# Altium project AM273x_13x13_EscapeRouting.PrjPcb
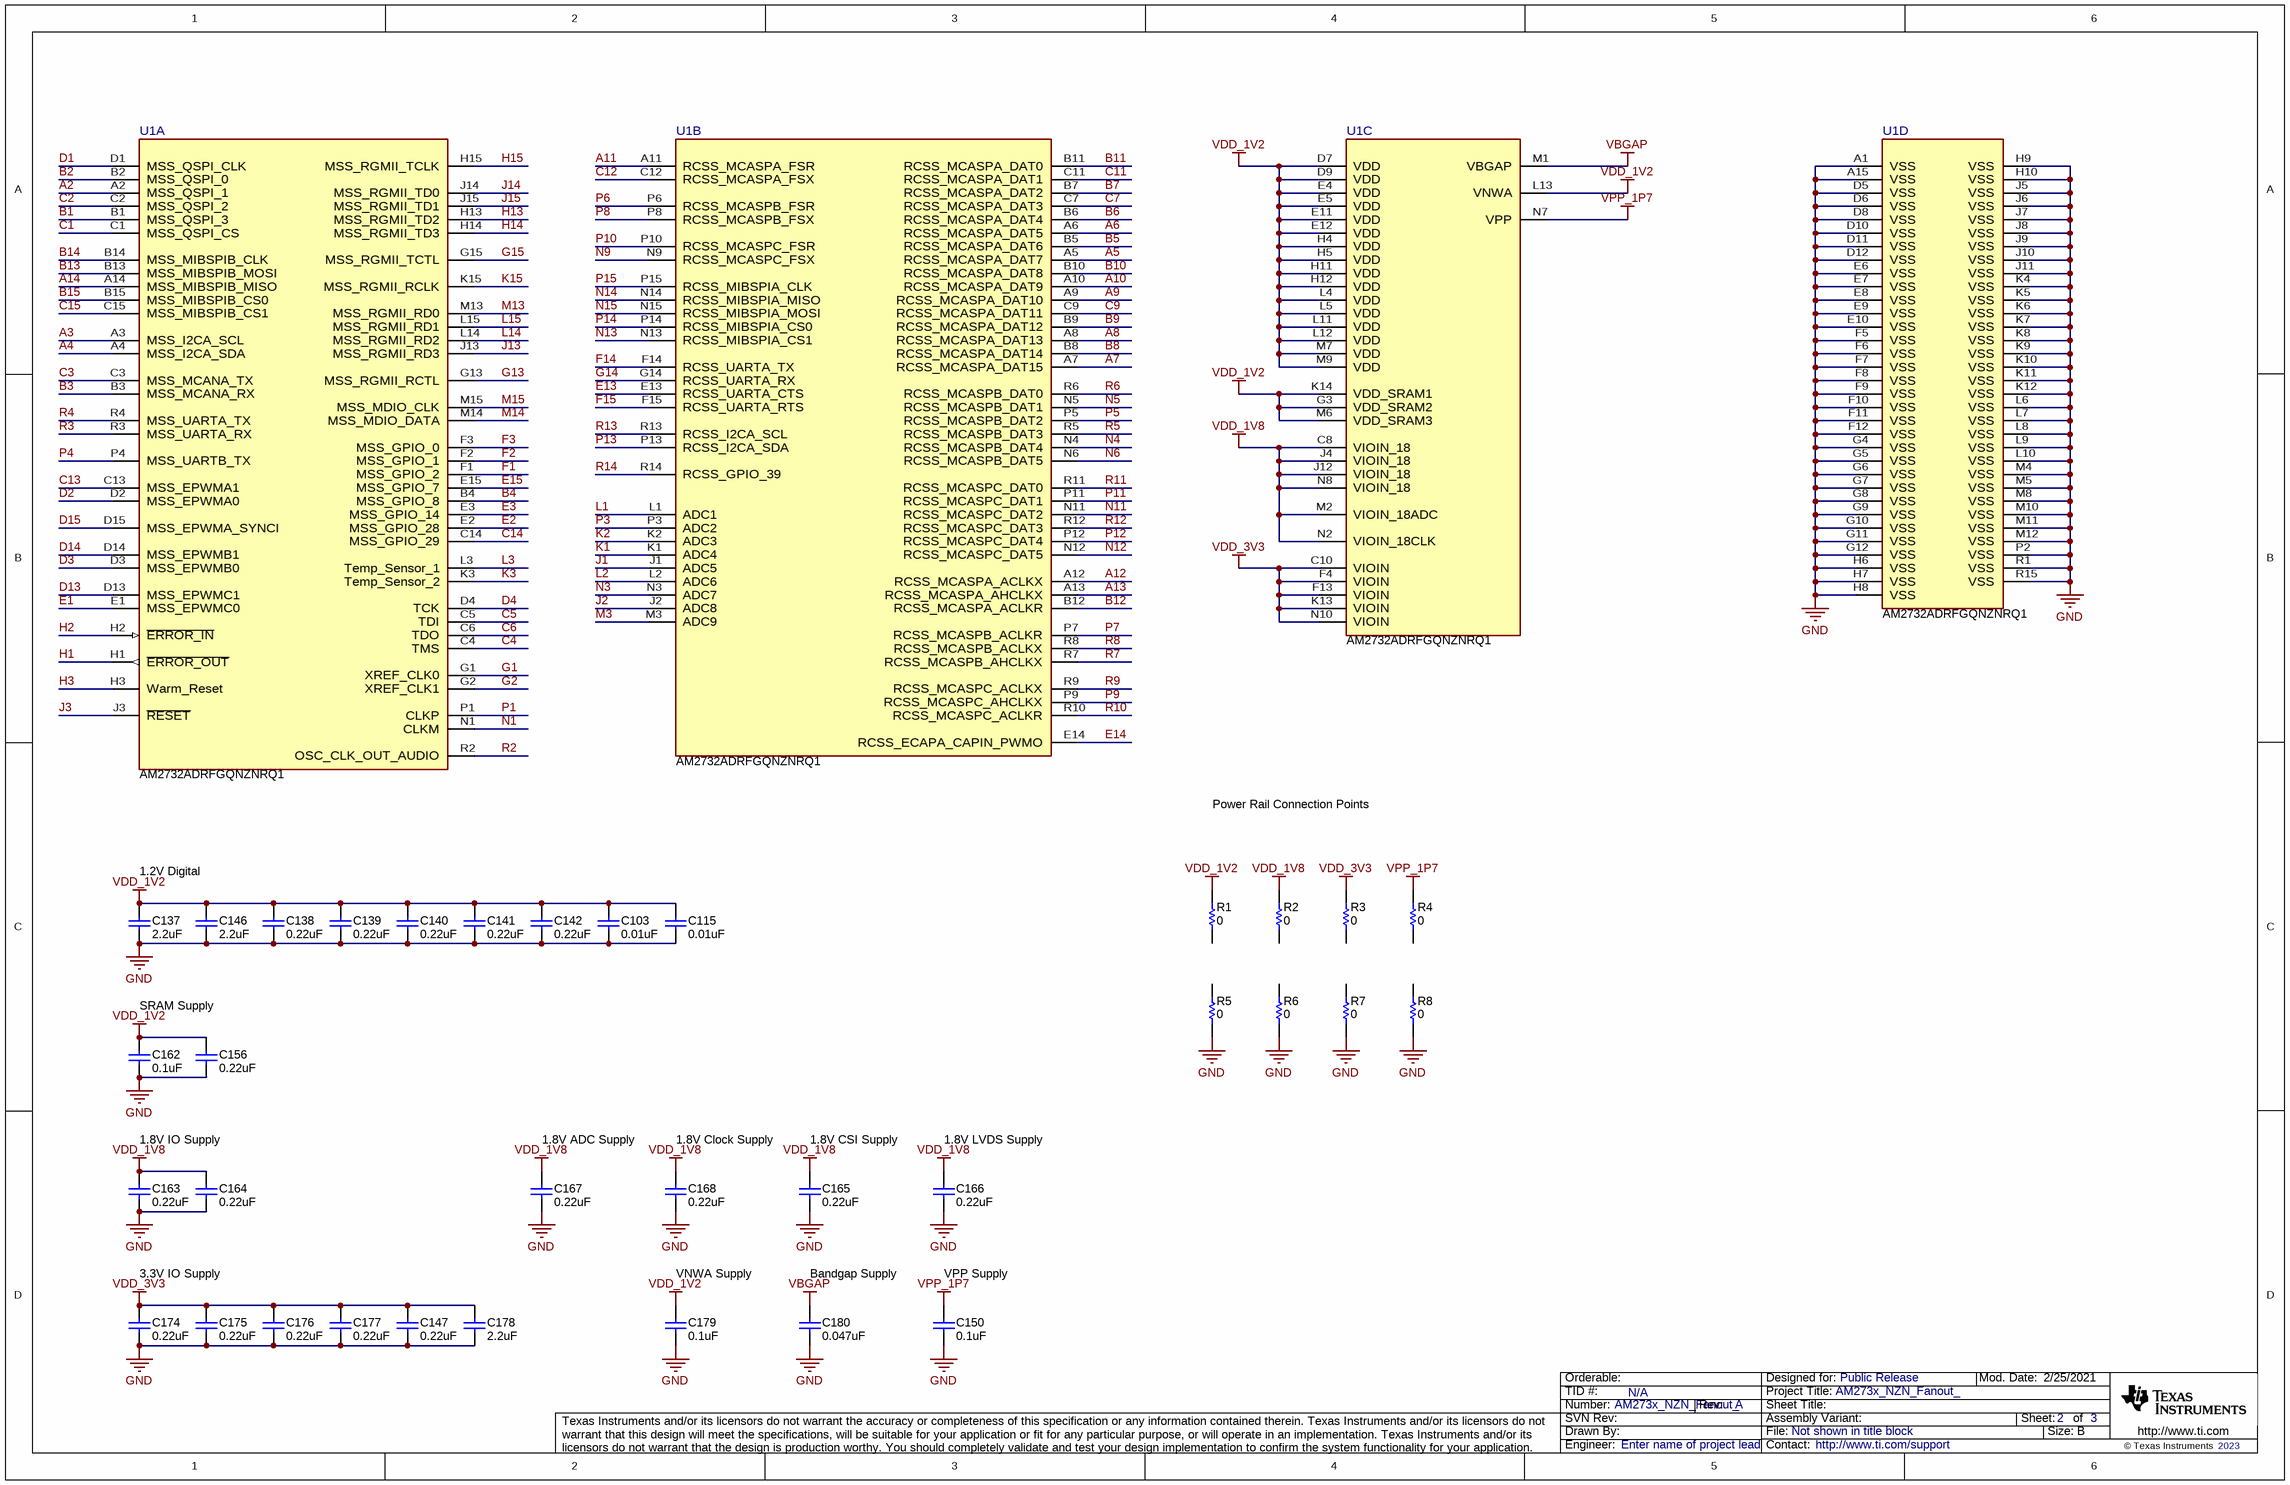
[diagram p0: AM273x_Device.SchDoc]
CopyrightYear: 2023; PCB_Layout: a02872566; PCB_Rev: A; PRJ_Customer: Public Release; PRJ_Engineer: Enter name of project lead; PRJ_Number: AM273x_NZN_Fanout_; PRJ_Title: AM273x_NZN_Fanout_; SCH_Rev: A; TechSupport: http://www.ti.com/support; TID: N/A
2 sheets, 42 parts. Net scope: global (net labels, ports and power ports of the same name join across sheets).
Board file: AM273x_13x13_EscapeRouting.PcbDoc
Sheets:
  AM273x_Device.SchDoc
  AM273x_13x13_EscapeRouting_Hardware.SchDoc

## Sheet AM273x_Device.SchDoc
size 431 x 279 mm; Date: Not shown in title block; ApprovedBy: Not shown in title block; CheckedBy: Not shown in title block; Author: Not shown in title block; CompanyName: Not shown in title block; Engineer: Not shown in title block; Organization: Not shown in title block; Address1: Not shown in title block; Address2: Not shown in title block; Address3: Not shown in title block; Address4: Not shown in title block; DocumentNumber: 2; Revision: Use project parameter SCH_Rev; SheetNumber: 2; SheetTotal: 3; PageSetup: Record=PageOptions¦CenterHorizontal=True¦CenterVertical=True¦PrintScale=1.00¦XCorrection=1.00¦YCorrection=1.00¦PrintKind=0¦BorderSize=5000000¦LeftOffset=0¦BottomOffset=0¦Orientation=2¦PaperLength=1000¦PaperWidth=1000¦Scale=100¦PaperSource=15¦PrintQuality=600¦MediaType=1¦DitherType=10¦PaperKind=Letter¦PrintScaleMode=1

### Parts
C103  ValueDisplayed: 0.01uF  [0402]  (hidden comment: CGA2B3X7R1H103K050BB)
C115  ValueDisplayed: 0.01uF  [0402]  (hidden comment: CGA2B3X7R1H103K050BB)
C137  ValueDisplayed: 2.2uF  [0603]  (hidden comment: GRM188R61C225KAAD)
C138  ValueDisplayed: 0.22uF  [0402]  (hidden comment: GRM155R71A224KE01D)
C139  ValueDisplayed: 0.22uF  [0402]  (hidden comment: GRM155R71A224KE01D)
C140  ValueDisplayed: 0.22uF  [0402]  (hidden comment: GRM155R71A224KE01D)
C141  ValueDisplayed: 0.22uF  [0402]  (hidden comment: GRM155R71A224KE01D)
C142  ValueDisplayed: 0.22uF  [0402]  (hidden comment: GRM155R71A224KE01D)
C146  ValueDisplayed: 2.2uF  [0603]  (hidden comment: GRM188R61C225KAAD)
C147  ValueDisplayed: 0.22uF  [0402]  (hidden comment: GRM155R71A224KE01D)
C150  ValueDisplayed: 0.1uF  [0402]  (hidden comment: GCM155R71C104KA55D)
C156  ValueDisplayed: 0.22uF  [0402]  (hidden comment: GRM155R71A224KE01D)
C162  ValueDisplayed: 0.1uF  [0402]  (hidden comment: GCM155R71C104KA55D)
C163  ValueDisplayed: 0.22uF  [0402]  (hidden comment: GRM155R71A224KE01D)
C164  ValueDisplayed: 0.22uF  [0402]  (hidden comment: GRM155R71A224KE01D)
C165  ValueDisplayed: 0.22uF  [0402]  (hidden comment: GRM155R71A224KE01D)
C166  ValueDisplayed: 0.22uF  [0402]  (hidden comment: GRM155R71A224KE01D)
C167  ValueDisplayed: 0.22uF  [0402]  (hidden comment: GRM155R71A224KE01D)
C168  ValueDisplayed: 0.22uF  [0402]  (hidden comment: GRM155R71A224KE01D)
C174  ValueDisplayed: 0.22uF  [0402]  (hidden comment: GRM155R71A224KE01D)
C175  ValueDisplayed: 0.22uF  [0402]  (hidden comment: GRM155R71A224KE01D)
C176  ValueDisplayed: 0.22uF  [0402]  (hidden comment: GRM155R71A224KE01D)
C177  ValueDisplayed: 0.22uF  [0402]  (hidden comment: GRM155R71A224KE01D)
C178  ValueDisplayed: 2.2uF  [0603]  (hidden comment: GRM188R61C225KAAD)
C179  ValueDisplayed: 0.1uF  [0402]  (hidden comment: GCM155R71C104KA55D)
C180  ValueDisplayed: 0.047uF  [0402]  (hidden comment: CGA2B3X7R1H473K050BB)
R1  ValueDisplayed: 0  [5106]  (hidden comment: 5106)
R2  ValueDisplayed: 0  [5106]  (hidden comment: 5106)
R3  ValueDisplayed: 0  [5106]  (hidden comment: 5106)
R4  ValueDisplayed: 0  [5106]  (hidden comment: 5106)
R5  ValueDisplayed: 0  [5106]  (hidden comment: 5106)
R6  ValueDisplayed: 0  [5106]  (hidden comment: 5106)
R7  ValueDisplayed: 0  [5106]  (hidden comment: 5106)
R8  ValueDisplayed: 0  [5106]  (hidden comment: 5106)
U1  AM2732ADRFGQNZNRQ1  [NZN0225A-MFG]  (parts A,B,C,D of 4)

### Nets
GND: C103.1 C115.1 C137.1 C138.1 C139.1 C140.1 C141.1 C142.1 C146.1 C147.1 C150.1 C156.1 C162.1 C163.1 C164.1 C165.1 C166.1 C167.1 C168.1 C174.1 C175.1 C176.1 C177.1 C178.1 C179.1 C180.1 R5.1 R6.1 R7.1 R8.1 U1.A1(VSS) U1.A15(VSS) U1.D5(VSS) U1.D6(VSS) U1.D8(VSS) U1.D10(VSS) U1.D11(VSS) U1.D12(VSS) U1.E6(VSS) U1.E7(VSS) U1.E8(VSS) U1.E9(VSS) U1.E10(VSS) U1.F5(VSS) U1.F6(VSS) U1.F7(VSS) U1.F8(VSS) U1.F9(VSS) U1.F10(VSS) U1.F11(VSS) U1.F12(VSS) U1.G4(VSS) U1.G5(VSS) U1.G6(VSS) U1.G7(VSS) U1.G8(VSS) U1.G9(VSS) U1.G10(VSS) U1.G11(VSS) U1.G12(VSS) U1.H6(VSS) U1.H7(VSS) U1.H8(VSS) U1.H9(VSS) U1.H10(VSS) U1.J5(VSS) U1.J6(VSS) U1.J7(VSS) U1.J8(VSS) U1.J9(VSS) U1.J10(VSS) U1.J11(VSS) U1.K4(VSS) U1.K5(VSS) U1.K6(VSS) U1.K7(VSS) U1.K8(VSS) U1.K9(VSS) U1.K10(VSS) U1.K11(VSS) U1.K12(VSS) U1.L6(VSS) U1.L7(VSS) U1.L8(VSS) U1.L9(VSS) U1.L10(VSS) U1.M4(VSS) U1.M5(VSS) U1.M8(VSS) U1.M10(VSS) U1.M11(VSS) U1.M12(VSS) U1.P2(VSS) U1.R1(VSS) U1.R15(VSS)
VBGAP: C180.2 U1.M1(VBGAP)
VDD_1V2: C103.2 C115.2 C137.2 C138.2 C139.2 C140.2 C141.2 C142.2 C146.2 C156.2 C162.2 C179.2 R1.2 U1.D7(VDD) U1.D9(VDD) U1.E4(VDD) U1.E5(VDD) U1.E11(VDD) U1.E12(VDD) U1.G3(VDD_SRAM2) U1.H4(VDD) U1.H5(VDD) U1.H11(VDD) U1.H12(VDD) U1.K14(VDD_SRAM1) U1.L4(VDD) U1.L5(VDD) U1.L11(VDD) U1.L12(VDD) U1.L13(VNWA) U1.M6(VDD_SRAM3) U1.M7(VDD) U1.M9(VDD)
VDD_1V8: C163.2 C164.2 C165.2 C166.2 C167.2 C168.2 R2.2 U1.C8(VIOIN_18) U1.J4(VIOIN_18) U1.J12(VIOIN_18) U1.M2(VIOIN_18ADC) U1.N2(VIOIN_18CLK) U1.N8(VIOIN_18)
VDD_3V3: C147.2 C174.2 C175.2 C176.2 C177.2 C178.2 R3.2 U1.C10(VIOIN) U1.F4(VIOIN) U1.F13(VIOIN) U1.K13(VIOIN) U1.N10(VIOIN)
VPP_1P7: C150.2 R4.2 U1.N7(VPP)
A2: U1.A2(MSS_QSPI_1)
A3: U1.A3(MSS_I2CA_SCL)
A4: U1.A4(MSS_I2CA_SDA)
A5: U1.A5(RCSS_MCASPA_DAT7)
A6: U1.A6(RCSS_MCASPA_DAT5)
A7: U1.A7(RCSS_MCASPA_DAT15)
A8: U1.A8(RCSS_MCASPA_DAT13)
A9: U1.A9(RCSS_MCASPA_DAT10)
A10: U1.A10(RCSS_MCASPA_DAT9)
A11: U1.A11(RCSS_MCASPA_FSR)
A12: U1.A12(RCSS_MCASPA_ACLKX)
A13: U1.A13(RCSS_MCASPA_AHCLKX)
A14: U1.A14(MSS_MIBSPIB_MISO)
B1: U1.B1(MSS_QSPI_3)
B2: U1.B2(MSS_QSPI_0)
B3: U1.B3(MSS_MCANA_RX)
B4: U1.B4(MSS_GPIO_8)
B5: U1.B5(RCSS_MCASPA_DAT6)
B6: U1.B6(RCSS_MCASPA_DAT4)
B7: U1.B7(RCSS_MCASPA_DAT2)
B8: U1.B8(RCSS_MCASPA_DAT14)
B9: U1.B9(RCSS_MCASPA_DAT12)
B10: U1.B10(RCSS_MCASPA_DAT8)
B11: U1.B11(RCSS_MCASPA_DAT0)
B12: U1.B12(RCSS_MCASPA_ACLKR)
B13: U1.B13(MSS_MIBSPIB_MOSI)
B14: U1.B14(MSS_MIBSPIB_CLK)
B15: U1.B15(MSS_MIBSPIB_CS0)
C1: U1.C1(MSS_QSPI_CS)
C2: U1.C2(MSS_QSPI_2)
C3: U1.C3(MSS_MCANA_TX)
C4: U1.C4(TMS)
C5: U1.C5(TDI)
C6: U1.C6(TDO)
C7: U1.C7(RCSS_MCASPA_DAT3)
C9: U1.C9(RCSS_MCASPA_DAT11)
C11: U1.C11(RCSS_MCASPA_DAT1)
C12: U1.C12(RCSS_MCASPA_FSX)
C13: U1.C13(MSS_EPWMA1)
C14: U1.C14(MSS_GPIO_29)
C15: U1.C15(MSS_MIBSPIB_CS1)
D1: U1.D1(MSS_QSPI_CLK)
D2: U1.D2(MSS_EPWMA0)
D3: U1.D3(MSS_EPWMB0)
D4: U1.D4(TCK)
D13: U1.D13(MSS_EPWMC1)
D14: U1.D14(MSS_EPWMB1)
D15: U1.D15(MSS_EPWMA_SYNCI)
E1: U1.E1(MSS_EPWMC0)
E2: U1.E2(MSS_GPIO_28)
E3: U1.E3(MSS_GPIO_14)
E13: U1.E13(RCSS_UARTA_CTS)
E14: U1.E14(RCSS_ECAPA_CAPIN_PWMO)
E15: U1.E15(MSS_GPIO_7)
F1: U1.F1(MSS_GPIO_2)
F2: U1.F2(MSS_GPIO_1)
F3: U1.F3(MSS_GPIO_0)
F14: U1.F14(RCSS_UARTA_TX)
F15: U1.F15(RCSS_UARTA_RTS)
G1: U1.G1(XREF_CLK0)
G2: U1.G2(XREF_CLK1)
G13: U1.G13(MSS_RGMII_RCTL)
G14: U1.G14(RCSS_UARTA_RX)
G15: U1.G15(MSS_RGMII_TCTL)
H1: U1.H1(~{ERROR_OUT})
H2: U1.H2(~{ERROR_IN})
H3: U1.H3(Warm_Reset)
H13: U1.H13(MSS_RGMII_TD2)
H14: U1.H14(MSS_RGMII_TD3)
H15: U1.H15(MSS_RGMII_TCLK)
J1: U1.J1(ADC5)
J2: U1.J2(ADC8)
J3: U1.J3(~{RESET})
J13: U1.J13(MSS_RGMII_RD3)
J14: U1.J14(MSS_RGMII_TD0)
J15: U1.J15(MSS_RGMII_TD1)
K1: U1.K1(ADC4)
K2: U1.K2(ADC3)
K3: U1.K3(Temp_Sensor_2)
K15: U1.K15(MSS_RGMII_RCLK)
L1: U1.L1(ADC1)
L2: U1.L2(ADC6)
L3: U1.L3(Temp_Sensor_1)
L14: U1.L14(MSS_RGMII_RD2)
L15: U1.L15(MSS_RGMII_RD1)
M3: U1.M3(ADC9)
M13: U1.M13(MSS_RGMII_RD0)
M14: U1.M14(MSS_MDIO_DATA)
M15: U1.M15(MSS_MDIO_CLK)
N1: U1.N1(CLKM)
N3: U1.N3(ADC7)
N4: U1.N4(RCSS_MCASPB_DAT4)
N5: U1.N5(RCSS_MCASPB_DAT1)
N6: U1.N6(RCSS_MCASPB_DAT5)
N9: U1.N9(RCSS_MCASPC_FSX)
N11: U1.N11(RCSS_MCASPC_DAT2)
N12: U1.N12(RCSS_MCASPC_DAT5)
N13: U1.N13(RCSS_MIBSPIA_CS1)
N14: U1.N14(RCSS_MIBSPIA_MISO)
N15: U1.N15(RCSS_MIBSPIA_MOSI)
P1: U1.P1(CLKP)
P3: U1.P3(ADC2)
P4: U1.P4(MSS_UARTB_TX)
P5: U1.P5(RCSS_MCASPB_DAT2)
P6: U1.P6(RCSS_MCASPB_FSR)
P7: U1.P7(RCSS_MCASPB_ACLKR)
P8: U1.P8(RCSS_MCASPB_FSX)
P9: U1.P9(RCSS_MCASPC_AHCLKX)
P10: U1.P10(RCSS_MCASPC_FSR)
P11: U1.P11(RCSS_MCASPC_DAT1)
P12: U1.P12(RCSS_MCASPC_DAT4)
P13: U1.P13(RCSS_I2CA_SDA)
P14: U1.P14(RCSS_MIBSPIA_CS0)
P15: U1.P15(RCSS_MIBSPIA_CLK)
R2: U1.R2(OSC_CLK_OUT_AUDIO)
R3: U1.R3(MSS_UARTA_RX)
R4: U1.R4(MSS_UARTA_TX)
R5: U1.R5(RCSS_MCASPB_DAT3)
R6: U1.R6(RCSS_MCASPB_DAT0)
R7: U1.R7(RCSS_MCASPB_AHCLKX)
R8: U1.R8(RCSS_MCASPB_ACLKX)
R9: U1.R9(RCSS_MCASPC_ACLKX)
R10: U1.R10(RCSS_MCASPC_ACLKR)
R11: U1.R11(RCSS_MCASPC_DAT0)
R12: U1.R12(RCSS_MCASPC_DAT3)
R13: U1.R13(RCSS_I2CA_SCL)
R14: U1.R14(RCSS_GPIO_39)

Not connected (* = marked no-connect by the designer): R1 1; R2 1; R3 1; R4 1; R5 2; R6 2; R7 2; R8 2

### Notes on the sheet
- Power Rail Connection Points
- 1.2V Digital
- SRAM Supply
- 1.8V IO Supply
- 1.8V ADC Supply
- 1.8V Clock Supply
- 1.8V CSI Supply
- (near C166) 1.8V LVDS Supply
- 3.3V IO Supply
- (near C179) VNWA Supply
- Bandgap Supply
- (near C150) VPP Supply

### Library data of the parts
C103 C115 = CMP-0006324-2: CAP, CERM, 0.01 uF, 50 V, +/- 10%, X7R, AEC-Q200 Grade 1, 0402; Manufacturer: TDK; TaMin_C: -55°C; ESR_ohm: 0.333065; Polarized: N; SizeAreaWB_mm2: 3; Value1: 0.333065 ohm; U/M: EA; Value: 0.01uF; TaMax_C: 125°C; SizeZ_mm: 0.6; SizeX_mm: 1; SizeY_mm: 0.5; Value2: 50V; AEC Qualified: Y; Cap_F: 10nF; IRMS_A: 323.373mA; AEC Category: Q200
C137 C146 C178 = CMP-0007338-4: CAP, CERM, 2.2 uF, 16 V, +/- 10%, X5R, 0603; Manufacturer: MuRata; TaMin_C: -55°C; Polarized: N; SizeAreaWB_mm2: 4.68; Value1: Unknown; U/M: EA; Value: 2.2uF; TaMax_C: 85°C; SizeZ_mm: 1; SizeX_mm: 1.6; SizeY_mm: 0.8; Value2: 16V; SizeArea_mm2: 1.28; Cap_F: 2.2µF; AEC Category: Q200
C138-C142 C147 C156 C163-C168 C174-C177 = CMP-0006630-1: CAP, CERM, 0.22 uF, 10 V, +/- 10%, X7R, 0402; Manufacturer: MuRata; TaMin_C: -55°C; Polarized: N; SizeAreaWB_mm2: 3; Value1: Unknown; U/M: EA; Value: 0.22uF; TaMax_C: 125°C; SizeZ_mm: 0.6; SizeX_mm: 1; SizeY_mm: 0.5; Value2: 10V; Cap_F: 220nF; AEC Category: Q200
C150 C162 C179 = CMP-0006351-2: CAP, CERM, 0.1 uF, 16 V, +/- 10%, X7R, 0402; Manufacturer: MuRata; TaMin_C: -55°C; Polarized: N; SizeAreaWB_mm2: 3; Value1: Unknown; U/M: EA; Value: 0.1uF; TaMax_C: 125°C; SizeZ_mm: 0.6; SizeX_mm: 1; SizeY_mm: 0.5; Value2: 16V; Cap_F: 100nF; AEC Category: Q200
C180 = CMP-0006330-2: CAP, CERM, 0.047 uF, 50 V, +/- 10%, X7R, AEC-Q200 Grade 1, 0402; Manufacturer: TDK; TaMin_C: -55°C; ESR_ohm: 0.06407; Polarized: N; SizeAreaWB_mm2: 3; Value1: 0.06407 ohm; U/M: EA; TaMax_C: 125°C; SizeZ_mm: 0.6; SizeX_mm: 1; SizeY_mm: 0.5; Value2: 50V; AEC Qualified: Y; Cap_F: 47nF; IRMS_A: 646.122mA; AEC Category: Q200
R1-R8 = CMP-0020833-2: RES, 0, 1%, 0.5 W, 0805; Manufacturer: Keystone; Power_W: 500mW; TempCo: ppm/C; U/M: EA; Value: 0; SizeX_mm: 2; SizeY_mm: 1.25; SizeZ_mm: 0.84; Value2: 0.5W; SizeArea_mm2: 2.5; AEC Qualified: N; AEC Category: Q200
U1 = CMP-0093973-1: TPR12; Manufacturer: Texas Instruments; AEC Qualified: Unknown; Standoff Height: 0.35mm; SizeZ_mm: 1.4mm

## Sheet AM273x_13x13_EscapeRouting_Hardware.SchDoc
size 431 x 279 mm; Date: Not shown in title block; ApprovedBy: Not shown in title block; CheckedBy: Not shown in title block; Author: Not shown in title block; CompanyName: Not shown in title block; Engineer: Not shown in title block; Organization: Not shown in title block; Address1: Not shown in title block; Address2: Not shown in title block; Address3: Not shown in title block; Address4: Not shown in title block; DocumentNumber: 3; Revision: Use project parameter SCH_Rev; SheetNumber: 3; SheetTotal: 6; PageSetup: Record=PageOptions¦CenterHorizontal=True¦CenterVertical=True¦PrintScale=1.00¦XCorrection=1.00¦YCorrection=1.00¦PrintKind=0¦BorderSize=5000000¦LeftOffset=0¦BottomOffset=0¦Orientation=2¦PaperLength=1000¦PaperWidth=1000¦Scale=100¦PaperSource=15¦PrintQuality=600¦MediaType=1¦DitherType=10¦PaperKind=Letter¦PrintScaleMode=1
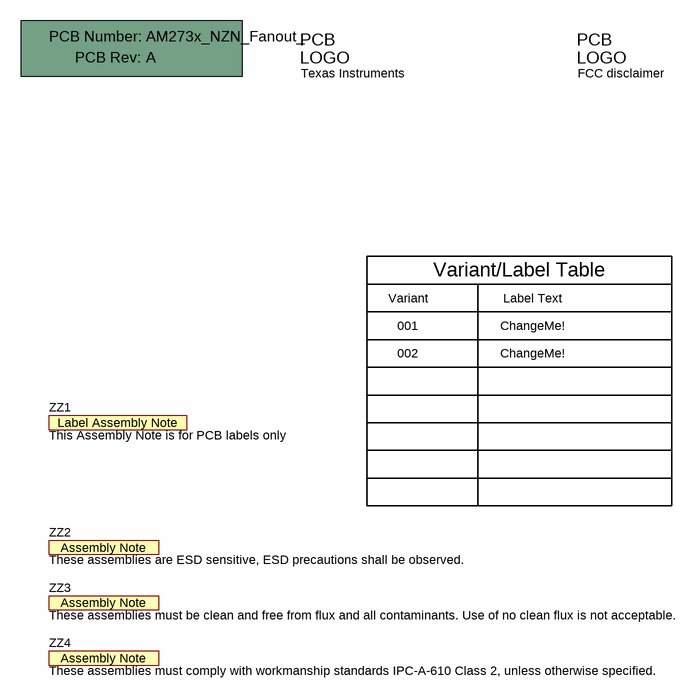
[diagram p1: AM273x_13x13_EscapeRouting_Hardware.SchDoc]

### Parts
!PCB  Printed Circuit Board  (value not drawn)  (mechanical)
Logo1  Texas Instruments  [TI_Stacked_Overlay_Small]  (no BOM)
Logo3  FCC disclaimer  [FCC_disclaimer]  (no BOM)
ZZ1  This Assembly Note is for PCB labels only  [AssemblyNoteLabel]  (no BOM)
ZZ2  These assemblies are ESD sensitive, ESD precautions shall be observed.  [AssemblyNote]  (no BOM)
ZZ3  These assemblies must be clean and free from flux and all contaminants. Use of no clean flux is not acceptable.  [AssemblyNote]  (no BOM)
ZZ4  These assemblies must comply with workmanship standards IPC-A-610 Class 2, unless otherwise specified.  [AssemblyNote]  (no BOM)

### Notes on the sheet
- Variant
- Variant/Label Table
- Label Text
- 001
- 002
- ChangeMe!

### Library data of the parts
!PCB = CMP-0003618-2: Manufacturer: Any; PartNumber: AM273x_NZN_Fanout_
Logo1 = CMP-0074838-1: Texas Instrument Corporate Signature; SymbolCreator: a0412235; Lib Reference: TI_Logo; Library Reference: Logo
Logo3 = CMP-0074847-1: FCC_disclaimer; Library Reference: Logo
ZZ1 = CMP-0003616-3
ZZ2 = CMP-0077236-1
ZZ3 = CMP-0077237-1
ZZ4 = CMP-0077238-1

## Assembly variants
001: not fitted FID1 FID2 FID3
